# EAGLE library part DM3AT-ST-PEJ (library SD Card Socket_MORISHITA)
DM3AT-SF-PEJ DM3AT series , microSD card socket Producted by Hirose(HRS).Co CC : card check (closed at insert ; short CC1 and CC2)
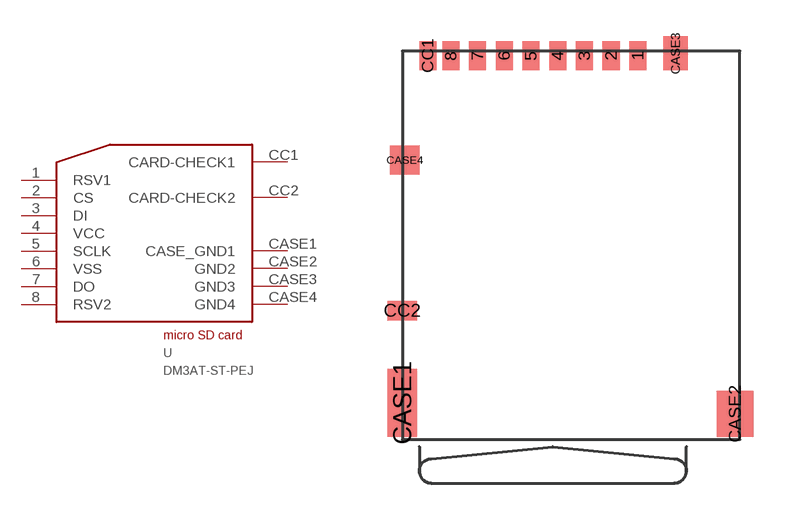
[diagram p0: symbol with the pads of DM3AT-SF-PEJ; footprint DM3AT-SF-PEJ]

Designator prefix -

## DM3AT-ST-PEJ  [DM3AT-SF-PEJ]
1  RSV1  nc
2  CS  in
3  DI  in
4  VCC  pwr
5  SCLK  in
6  VSS  pwr
7  DO  out
8  RSV2  nc
CASE1  CASE_GND1  pwr
CASE2  GND2  pwr
CASE3  GND3  pwr
CASE4  GND4  pwr
CC1  CARD-CHECK1
CC2  CARD-CHECK2

## Footprint DM3AT-SF-PEJ (pad centres in mm)
DM3AT-SF-PEJ DM3AT series , microSD card socket Producted by Hirose(HRS).Co CC : card check (closed at insert ; short CC1 and CC2)
smd 0.7 x 1.2: 1 0,0.6; 2 -1.1,0.6; 3 -2.2,0.6; 4 -3.3,0.6; 5 -4.4,0.6; 6 -5.5,0.6; 7 -6.6,0.6; 8 -7.7,0.6; CC1 -8.65,0.6
smd 1.2 x 2.8: CASE1 -9.7,-13.7
smd 1.5 x 1.9: CASE2 4,-14.15
smd 1 x 1.4: CASE3 1.55,0.7
smd 1.2 x 1.2: CASE4 -9.6,-3.7
smd 1.2 x 0.8: CC2 -9.7,-9.9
